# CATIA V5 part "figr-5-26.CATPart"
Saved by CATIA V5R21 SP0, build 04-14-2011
Part number: Part1
Bounding box of the stored display mesh (mm): x -75 to 75, y -100 to 100, z 0 to 53
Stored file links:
  D:\CATIA V5R21 E-RESOURCES\CATIA-V5R21\catia-v5r21-prt\c05-catia-v5r20-prt\catia-v5r21-figr-5-26.CATPart
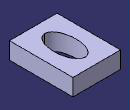
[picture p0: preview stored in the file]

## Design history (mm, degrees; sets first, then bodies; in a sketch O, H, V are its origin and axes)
Body1 (main body)
  Sketch1 on xy-plane, origin (0, 0, 0), H (1, 0, 0), V (0, 1, 0)
    line L1 (-75, 100) -> (75, 100)
    line L2 (75, 100) -> (75, -100)
    line L3 (75, -100) -> (-75, -100)
    line L4 (-75, -100) -> (-75, 100)
    axis line L5 (75, -100) -> (-75, 100)
    length L3 = 150
    length L2 = 200
    horizontal: L1 H, L3 H
    vertical: L2 V, L4 V
    midpoint: L5 O
  Pad1: profile Sketch1, direction (0, 0, 1), length 53
  Sketch2 on face of Pad1, origin (0, 0, 53), H (1, 0, 0), V (0, 1, 0)
    ellipse A1 centre (0, 0) semi-axes 63.781, 34.5424 rotation 270
    point P1 (0, -63.781)
    point P2 (34.5424, 0)
    coincidence: P1 V, P2 H, A1 P1, A1 P2
  Pocket1: profile Sketch2, direction (0, 0, -1), through (limit type 3)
